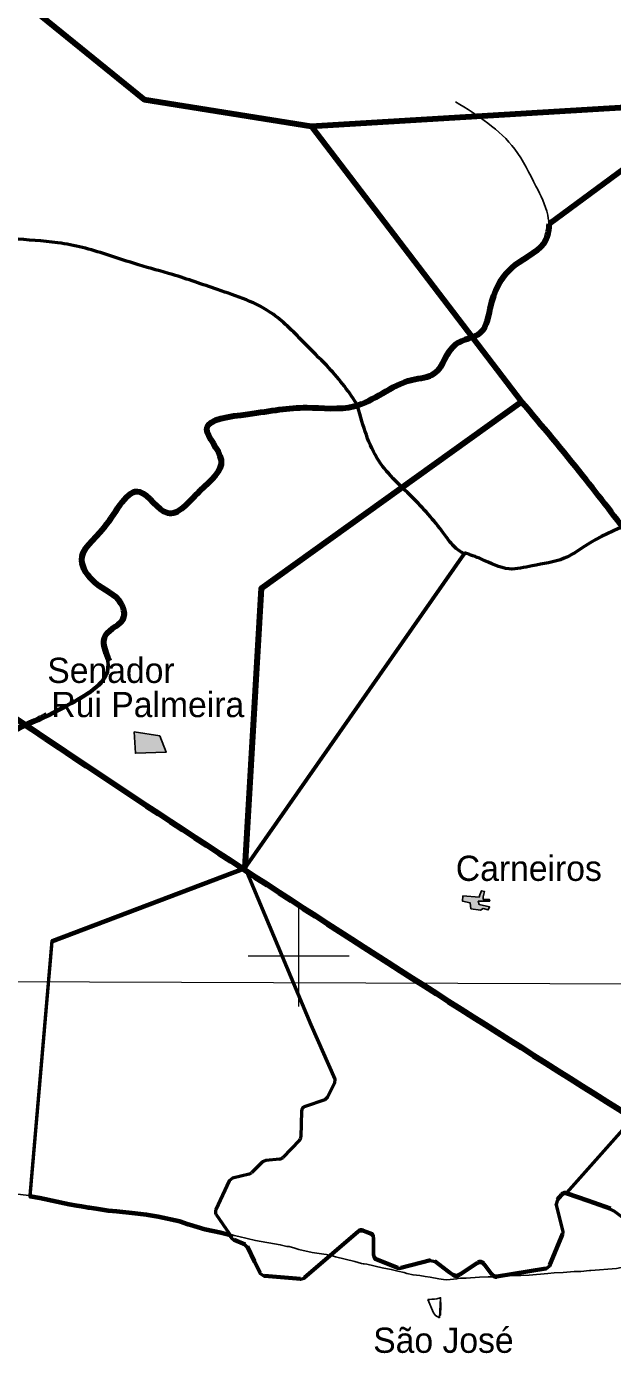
# Model space of a CAD drawing. Extents: x -1643653 to 4543381, y 1624270 to 13878484.
# Drawn here: x 669599 to 681227, y 8942036 to 8968437 of the extents above; entities that cross this region are included whole.
import ezdxf

# ---------------------------------------------------------------- set-up
doc = ezdxf.new("R2010")
doc.units = 0
doc.header["$LTSCALE"] = 200
for name, color, linetype, lineweight in [('1', 7, 'Continuous', 13), ('12', 7, 'Continuous', 25), ('2', 7, 'Continuous', 13), ('21', 7, 'Continuous', 25), ('24', 7, 'Continuous', 25), ('53', 7, 'Continuous', 106), ('58', 7, 'Continuous', 13), ('59', 7, 'Continuous', 53), ('60', 7, 'Continuous', 13), ('9', 7, 'Continuous', 90)]:
    doc.layers.add(name, color=color, linetype=linetype, lineweight=lineweight)
doc.layers.add('41', color=7, linetype='Continuous')

msp = doc.modelspace()

# ---------------------------------------------------------------- hatches: boundary and pattern name
at = {"layer": '21'}
for points in [[(671735.9, 8954446), (671760.9, 8954023.3), (672373, 8954044.2), (672243, 8954367.7)], [(678583.8, 8951169.2), (678261.7, 8951191), (678249.4, 8951088.7), (678404.6, 8951053.3), (678418.7, 8950935.7), (678608.1, 8950907.5), (678661.5, 8950941.2), (678763.6, 8950913.7), (678790.7, 8950974.2), (678582.5, 8951021.4), (678564.1, 8951086), (678791.6, 8951084.1), (678784.3, 8951122), (678663, 8951123.1), (678659.7, 8951172.4), (678690.9, 8951278.2), (678630.4, 8951293.9), (678595.5, 8951210.8)]]:
    msp.add_hatch(color=256, dxfattribs=at).paths.add_polyline_path(points)

# ---------------------------------------------------------------- linework, layer by layer
at = {"layer": '1'}
msp.add_line((565315.3, 8949866.8), (791497.7, 8949052.2), dxfattribs=at)
at = {"layer": '12'}
for points in [[(668899, 8945330), (669255.4, 8945287.2), (669478.1, 8945268.3), (669643.1, 8945246.3), (669863.8, 8945209.3), (670444.9, 8945082.7), (670594.5, 8945054.4), (670690.4, 8945040.8)], [(670690.4, 8945040.8), (670793.7, 8945026.2), (670822.8, 8945019.5)], [(670822.8, 8945019.5), (670847.1, 8945013.9), (670933.2, 8945004.3), (670978.2, 8944997.2)], [(670978.2, 8944997.2), (671219.6, 8944959.2), (671390.7, 8944942.2)], [(671390.7, 8944942.2), (671755.8, 8944906), (671982.5, 8944878.3), (672015.3, 8944872.6)], [(672015.3, 8944872.6), (672208.8, 8944838.9), (672642.8, 8944742.4), (672807.7, 8944686.1), (672835.8, 8944677.4)], [(672835.8, 8944677.4), (673135, 8944584.9), (673452.2, 8944518.2), (673636.9, 8944471), (673680.2, 8944467), (673722.5, 8944456.8), (673814.7, 8944434.5)], [(673814.7, 8944434.5), (674141.4, 8944355.7), (674634.1, 8944270.1), (674766.5, 8944235.9), (674806.9, 8944235.5)], [(674806.9, 8944235.5), (674811.8, 8944235.4), (674924.1, 8944202)], [(674924.1, 8944202), (675002.8, 8944178.6), (675266.7, 8944118.2), (675501.9, 8944084.2)], [(675501.9, 8944084.2), (675549.2, 8944077.4), (675673.7, 8944051.4), (675728.2, 8944031.1), (676117.5, 8943940.8), (676244.7, 8943899.9), (676282.8, 8943893.9), (676298, 8943891.5)], [(676298, 8943891.5), (676354.6, 8943882.5), (676657.8, 8943812.3), (676836.6, 8943782), (676967, 8943748), (677095.8, 8943720.8), (677145.9, 8943703.2), (677271.9, 8943671.8), (677401.8, 8943658.6), (677511.4, 8943642.7)], [(680796, 8943762.2), (681305.7, 8943800.9), (681399.5, 8943819.2), (681734.6, 8943857.4), (681767.5, 8943859.3)], [(677511.4, 8943642.7), (677607.8, 8943628.7), (677782.8, 8943592.4), (677875.1, 8943578.3), (677942.5, 8943578.2)], [(677942.5, 8943578.2), (678138.2, 8943595.7), (678165.3, 8943599.8), (678210.4, 8943606.5)], [(678210.4, 8943606.5), (678223.5, 8943608.4), (678326.7, 8943610.6), (678591.7, 8943628.6), (678760.3, 8943631.9)], [(678760.3, 8943631.9), (678797.8, 8943632.6), (678870.7, 8943637.5)], [(678870.7, 8943637.5), (679230.8, 8943661.7), (679406.8, 8943661.9), (679572.2, 8943670.5), (679942.5, 8943703.3)], [(679942.5, 8943703.3), (680069.1, 8943714.6), (680249.7, 8943722.5), (680468, 8943742.1), (680601.6, 8943742.7), (680771.8, 8943760.4), (680796, 8943762.2)]]:
    msp.add_lwpolyline(points, dxfattribs=at)
at = {"layer": '2'}
for p, q in [((675000, 8949000), (675000, 8951000)), ((674000, 8950000), (676000, 8950000))]:
    msp.add_line(p, q, dxfattribs=at)
at = {"layer": '21'}
for points in [[(671735.9, 8954446), (671760.9, 8954023.3), (672373, 8954044.2), (672243, 8954367.7)], [(678583.8, 8951169.2), (678261.7, 8951191), (678249.4, 8951088.7), (678404.6, 8951053.3), (678418.7, 8950935.7), (678608.1, 8950907.5), (678661.5, 8950941.2), (678763.6, 8950913.7), (678790.7, 8950974.2), (678582.5, 8951021.4), (678564.1, 8951086), (678791.6, 8951084.1), (678784.3, 8951122), (678663, 8951123.1), (678659.7, 8951172.4), (678690.9, 8951278.2), (678630.4, 8951293.9), (678595.5, 8951210.8)]]:
    msp.add_lwpolyline(points, close=True, dxfattribs=at)
for points in [[(677564.5, 8943182.9), (677599.4, 8943181.8), (677648.6, 8943194.1), (677696.2, 8943191), (677743.9, 8943194.8), (677811.3, 8943218), (677815.7, 8943218.5), (677793.3, 8942820.7)], [(677793.3, 8942820.7), (677714, 8942864.2), (677676.2, 8942918.7), (677564.5, 8943182.9)]]:
    msp.add_lwpolyline(points, dxfattribs=at)
at = {"layer": '21', "lineweight": 13}
for points in [[(677818.6, 8943060.4), (677817.1, 8942876.8), (677800.3, 8942857.8), (677789.7, 8942835.5), (677793.3, 8942820.7)], [(677811.4, 8943218.2), (677807.9, 8943209.5), (677818.9, 8943095.6), (677818.6, 8943060.4)]]:
    msp.add_lwpolyline(points, dxfattribs=at)
at = {"layer": '24'}
msp.add_spline([(665209.5, 8949437.1), (665261.8, 8949907.3), (665888.8, 8950560.5), (666750.9, 8951187.5), (667665.3, 8951814.5), (668344.5, 8952363.1), (668788.7, 8952911.7), (669180.6, 8953564.9), (669154.4, 8954270.2), (669755.3, 8954662.1), (670486.8, 8955027.9), (671218.3, 8955785.5), (671166.1, 8956360.3), (671531.8, 8956726), (671479.6, 8956987.3), (670957.1, 8957405.3), (670695.8, 8957849.4), (671139.9, 8958502.5), (671845.3, 8959207.9), (672394, 8958789.9), (673047.1, 8959234), (673465.1, 8959834.9), (673177.7, 8960461.9), (673987.6, 8960749.3), (675163.2, 8960879.9), (676103.7, 8960906.1), (677253.2, 8961428.6), (677697.4, 8961559.2), (678115.4, 8962133.9), (678611.8, 8962369.1), (678820.8, 8962919.9), (679291, 8963704.1), (679918, 8964226.8), (679944.1, 8964697.3), (679709, 8965272.3), (679291, 8966004.2), (678115.4, 8966945.2)], degree=3, dxfattribs=at)
at = {"layer": '53'}
msp.add_line((687996.5, 8970447.8), (679978.5, 8964524.9), dxfattribs=at)
for points in [[(671243.6, 8955851), (671166.1, 8956360.3), (671531.8, 8956726), (671479.6, 8956987.3), (670957.1, 8957405.3), (670695.8, 8957849.4), (671139.9, 8958502.5), (671845.3, 8959207.9), (672394, 8958789.9), (673047.1, 8959234), (673465.1, 8959834.9), (673177.7, 8960461.9), (673987.6, 8960749.3), (675163.2, 8960879.9), (676103.7, 8960906.1), (677253.2, 8961428.6), (677697.4, 8961559.2), (678115.4, 8962133.9), (678611.8, 8962369.1), (678820.8, 8962919.9), (679291, 8963704.1), (679918, 8964226.8), (679978.5, 8964524.9)], [(665209.5, 8949437.1), (665261.8, 8949907.3), (665888.8, 8950560.5), (666750.9, 8951187.5), (667665.3, 8951814.5), (668344.5, 8952363.1), (668788.7, 8952911.7), (669180.6, 8953564.9), (669154.4, 8954270.2), (669755.3, 8954662.1), (670000.9, 8954785.2)]]:
    msp.add_spline(points, degree=3, dxfattribs=at)
at = {"layer": '58'}
for points in [[(676174.9, 8960921), (676168.8, 8960893.4), (676168.8, 8960893.4), (676174.9, 8960894.8)], [(678278.9, 8957978.6), (678286.7, 8957989.8), (678291, 8957999)]]:
    msp.add_lwpolyline(points, dxfattribs=at)
for points in [[(655983.7, 8975399.4), (656923, 8974848.7), (657608.5, 8974464.4), (658343, 8973736.5), (658963.6, 8973136.3), (659596.6, 8972485.1), (660330.5, 8971655.5), (660495.7, 8971591.2), (661115.6, 8970863.8), (661404.1, 8970086.9), (661693.8, 8969526.2), (662110.5, 8968901.3), (662312.2, 8968544.4), (662816.6, 8967664.9), (663042.2, 8967040.8), (663203.6, 8966302.6), (663365.3, 8965640.7), (663833.2, 8965053.8), (664099.5, 8964849.2), (664772, 8964426.8), (665496.3, 8964144), (666463.4, 8964000.2), (667623.1, 8964148), (668184.3, 8964285.6), (669317.4, 8964230), (670221.1, 8964150), (671187.7, 8963917.1), (671823.3, 8963711.1), (672497.1, 8963517.5), (673386.9, 8963221.4), (674492.1, 8962733.6), (675125.5, 8962146), (675556, 8961711.9), (676150.3, 8960959.1), (676174.9, 8960921)], [(676174.9, 8960894.8), (676589.7, 8959824.8), (677298.5, 8959058.9), (677905.7, 8958344.2), (678108.1, 8958101.8), (678278.9, 8957978.6)], [(678291, 8957999), (678628.8, 8957871.5), (679175.3, 8957678.5), (679634.1, 8957740.2), (680271.7, 8957890.1), (680680.6, 8958130.1), (682556.7, 8958821.8), (683435.7, 8958881.7), (684580.7, 8958673.6), (685598.3, 8958453.2)]]:
    msp.add_spline(points, degree=3, dxfattribs=at)
at = {"layer": '59'}
for p, q in [((675713, 8947474.9), (675575.4, 8947196.5)), ((675517.3, 8947145.9), (675125.9, 8947015.5)), ((675057.6, 8946923.6), (675042.4, 8946412.2)), ((675057.6, 8946923.6), (675042.4, 8946412.2)), ((675014.8, 8946346.2), (674685, 8946000.3)), ((675014.8, 8946346.2), (674685, 8946000.3)), ((674283.9, 8945916), (674062, 8945697.8)), ((674621.8, 8945969.8), (674344.8, 8945944.2)), ((674015.4, 8945671.9), (673688.4, 8945593)), ((673621.4, 8945538.3), (673355.6, 8944972)), ((680134, 8945176.2), (680214.2, 8945273)), ((673363.7, 8944872.9), (673675, 8944419.4)), ((673363.7, 8944872.9), (673640.2, 8944470.1)), ((680241.8, 8944556.7), (680113.8, 8945089)), ((673716.6, 8944384.7), (673935.5, 8944286.7)), ((675110.8, 8943630.1), (676179.1, 8944546.1)), ((676280.2, 8944563.4), (676422.8, 8944508.3)), ((676422.8, 8944482.2), (676280.2, 8944537.3)), ((676486.8, 8944415.1), (676486.8, 8944082.3)), ((676486.8, 8944056.2), (676486.8, 8944388.9)), ((679978.9, 8943872.2), (680237, 8944495.1)), ((676550.7, 8943989.1), (676967.6, 8943827.5)), ((677029.2, 8943824), (677616.1, 8943978.3)), ((678196.5, 8943692), (678546.5, 8943924.4)), ((678546.5, 8943898.2), (678196.5, 8943665.9)), ((678682.2, 8943900.5), (678836.2, 8943692)), ((678836.2, 8943665.9), (678682.2, 8943874.3)), ((678932.8, 8943652.8), (679902.7, 8943811.8)), ((674319.5, 8943668.1), (675037.1, 8943606.4))]:
    msp.add_line(p, q, dxfattribs=at)
for points in [[(670690.4, 8945014.6), (670594.5, 8945028.2), (670444.9, 8945056.6), (669863.8, 8945183.2), (669668.8, 8945215.8), (669670.4, 8945225.3), (670109.7, 8950279.6), (673931.9, 8951728.3), (678286.7, 8957963.6), (678291, 8957972.9)], [(678286.7, 8957989.8), (673931.9, 8951754.5), (675240.6, 8948634.2)], [(680324.2, 8945303.6), (688585, 8954592.4), (688741.1, 8957552.5)], [(680324.2, 8945303.6), (688585, 8954592.4), (688741.1, 8957552.5)], [(669670.4, 8945251.4), (670109.7, 8950305.8), (673931.9, 8951754.5)], [(673931.9, 8951754.5), (675240.6, 8948634.2), (675717.3, 8947553.5)], [(675240.6, 8948634.2), (675717.3, 8947553.5), (675713, 8947474.9), (675575.4, 8947196.5), (675517.3, 8947145.9), (675125.9, 8947015.5)], [(674621.8, 8945969.8), (674344.8, 8945944.2), (674283.9, 8945916), (674062, 8945697.8)], [(674015.4, 8945671.9), (673688.4, 8945593), (673621.4, 8945538.3), (673355.6, 8944972)], [(670690.4, 8945040.8), (670594.5, 8945054.4), (670444.9, 8945082.7), (669863.8, 8945209.3), (669668.8, 8945241.9)], [(680214.2, 8945246.8), (680134, 8945150.1), (680113.8, 8945062.9), (680241.8, 8944530.5), (680237, 8944468.9), (679978.9, 8943846), (679902.7, 8943785.6), (678932.8, 8943626.6)], [(681194.6, 8944999.3), (680745, 8945156.4), (680324.2, 8945303.6)], [(684892.7, 8942987.2), (684448.1, 8942951.1), (684389.5, 8942964.5), (683513.2, 8943477.6), (683428.9, 8943485.5), (683149.4, 8943385.1), (683078.6, 8943386.3), (681940.2, 8943839.3), (681879.7, 8943909.7), (681729.7, 8944557.4), (681692.2, 8944614.9), (681259.8, 8944938.4), (681194.6, 8944973.1), (680745, 8945130.3), (680324.2, 8945277.4)], [(670822.8, 8945019.5), (670793.7, 8945026.2), (670690.4, 8945040.8)], [(670822.8, 8944993.3), (670793.7, 8945000), (670690.4, 8945014.6)], [(670978.2, 8944997.2), (670933.2, 8945004.3), (670847.1, 8945013.9), (670822.8, 8945019.5)], [(670978.2, 8944971.1), (670933.2, 8944978.2), (670847.1, 8944987.8), (670822.8, 8944993.3)], [(671390.7, 8944942.2), (671219.6, 8944959.2), (670978.2, 8944997.2)], [(671390.7, 8944916.1), (671219.6, 8944933), (670978.2, 8944971.1)], [(672015.3, 8944872.6), (671982.5, 8944878.3), (671755.8, 8944906), (671390.7, 8944942.2)], [(672015.3, 8944846.5), (671982.5, 8944852.2), (671755.8, 8944879.8), (671390.7, 8944916.1)], [(672835.8, 8944677.4), (672807.7, 8944686.1), (672642.8, 8944742.4), (672208.8, 8944838.9), (672015.3, 8944872.6)], [(672835.8, 8944651.2), (672807.7, 8944659.9), (672642.8, 8944716.3), (672208.8, 8944812.7), (672015.3, 8944846.5)], [(673640.2, 8944470.7), (673636.9, 8944471), (673452.2, 8944518.2), (673135, 8944584.9), (672835.8, 8944677.4)], [(673640.2, 8944444.5), (673636.9, 8944444.8), (673452.2, 8944492.1), (673135, 8944558.8), (672835.8, 8944651.2)], [(676179.1, 8944519.9), (675110.8, 8943603.9), (675037.1, 8943580.2), (674319.5, 8943642), (674238.3, 8943697.5), (674125.3, 8943927.1), (673984.4, 8944213.4), (673935.5, 8944260.6), (673716.6, 8944358.5), (673675, 8944393.2), (673640, 8944444.3), (673640.2, 8944444.5)], [(673984.4, 8944239.6), (674125.3, 8943953.3), (674238.3, 8943723.6)], [(678045.7, 8943671.1), (677962, 8943735.4), (677702.4, 8943934.8), (677616.1, 8943952.2), (677029.2, 8943797.8), (676967.6, 8943801.3), (676550.7, 8943962.9)], [(677702.4, 8943960.9), (677962, 8943761.6), (678045.7, 8943697.2)]]:
    msp.add_lwpolyline(points, dxfattribs=at)
for centre, radius, start, end in [((675157.6, 8946920.6), 100, 108.43497, 178.29512), ((675157.6, 8946920.6), 100, 108.43497, 178.29723), ((674942.5, 8946415.2), 100, 316.36201, 358.29723), ((674612.7, 8946069.4), 100, 275.26498, 316.36201), ((673991.9, 8945769.1), 100, 283.57688, 314.51592), ((673991.9, 8945769.1), 100, 283.57688, 314.51592), ((680291.2, 8945209.2), 100, 70.7277, 140.34605), ((680291.2, 8945183), 100, 70.7277, 140.34605), ((673446.2, 8944929.5), 100, 154.86041, 214.46341), ((676244.1, 8944470.2), 100, 68.88566, 130.61183), ((676244.1, 8944444), 100, 68.88566, 130.61183), ((676386.8, 8944415.1), 100, 0, 68.88566), ((676386.8, 8944388.9), 100, 0, 68.88566), ((676586.8, 8944082.3), 100, 180, 248.81474), ((676586.8, 8944056.2), 100, 180, 248.81474), ((678601.8, 8943841.1), 100, 36.45572, 123.58272), ((678601.8, 8943814.9), 100, 36.45572, 123.58272), ((678124.8, 8943800.1), 129.8, 232.47373, 303.58145), ((678124.8, 8943774), 129.8, 232.47373, 303.58145), ((678916.6, 8943751.5), 100, 216.45573, 279.30864), ((678916.6, 8943725.3), 100, 216.45573, 279.30864)]:
    msp.add_arc(centre, radius, start, end, dxfattribs=at)
for points in [[(676174.9, 8960921), (676150.3, 8960959.1), (675556, 8961711.9), (675125.5, 8962146), (674492.1, 8962733.6), (673386.9, 8963221.4), (672497.1, 8963517.5), (671823.3, 8963711.1), (671187.7, 8963917.1), (670221.1, 8964150), (669317.4, 8964230), (668184.3, 8964285.6), (667623.1, 8964148), (666463.4, 8964000.2), (665496.3, 8964144), (664772, 8964426.8), (664099.5, 8964849.2), (663833.2, 8965053.8), (663365.3, 8965640.7), (663203.6, 8966302.6), (663042.2, 8967040.8), (662816.6, 8967664.9), (662312.2, 8968544.4), (662110.5, 8968901.3), (661693.8, 8969526.2), (661404.1, 8970086.9), (661115.6, 8970863.8), (660495.7, 8971591.2), (660330.5, 8971655.5), (659596.6, 8972485.1), (658963.6, 8973136.3), (658343, 8973736.5), (657608.5, 8974464.4), (656923, 8974848.7), (655983.7, 8975399.4)], [(665209.5, 8949437.1), (665261.8, 8949907.3), (665888.8, 8950560.5), (666750.9, 8951187.5), (667665.3, 8951814.5), (668344.5, 8952363.1), (668788.7, 8952911.7), (669180.6, 8953564.9), (669154.4, 8954270.2), (669755.3, 8954662.1), (670486.8, 8955027.9), (671218.3, 8955785.5), (671166.1, 8956360.3), (671531.8, 8956726), (671479.6, 8956987.3), (670957.1, 8957405.3), (670695.8, 8957849.4), (671139.9, 8958502.5), (671845.3, 8959207.9), (672394, 8958789.9), (673047.1, 8959234), (673465.1, 8959834.9), (673177.7, 8960461.9), (673987.6, 8960749.3), (675163.2, 8960879.9), (676103.7, 8960906.1), (676174.9, 8960921)], [(676174.9, 8960894.8), (676103.7, 8960879.9), (675163.2, 8960853.8), (673987.6, 8960723.2), (673177.7, 8960435.8), (673465.1, 8959808.8), (673047.1, 8959207.9), (672394, 8958763.8), (671845.3, 8959181.8), (671139.9, 8958476.4), (670695.8, 8957823.2), (670957.1, 8957379.1), (671479.6, 8956961.1), (671531.8, 8956699.9), (671166.1, 8956334.1), (671218.3, 8955759.3), (670486.8, 8955001.7), (669755.3, 8954636), (669154.4, 8954244.1), (669180.6, 8953538.7), (668788.7, 8952885.6), (668344.5, 8952337), (667665.3, 8951788.3), (666750.9, 8951161.3), (665888.8, 8950534.3), (665261.8, 8949881.2), (665209.5, 8949410.9)], [(678291, 8957972.9), (678108.1, 8958101.8), (677905.7, 8958344.2), (677298.5, 8959058.9), (676589.7, 8959824.8), (676174.9, 8960894.8)], [(685598.3, 8958453.2), (684580.7, 8958673.6), (683435.7, 8958881.7), (682556.7, 8958821.8), (680680.6, 8958130.1), (680271.7, 8957890.1), (679634.1, 8957740.2), (679175.3, 8957678.5), (678628.8, 8957871.5), (678291, 8957999)]]:
    msp.add_spline(points, degree=3, dxfattribs=at)
at = {"layer": '60', "lineweight": 25}
msp.add_spline([(814781, 9009175.5), (814787.2, 9009173.4), (814796.9, 9009173.4), (814799.4, 9009172.4), (814805.1, 9009174.5), (814805.6, 9009176.5), (814811.7, 9009179.5), (814811.7, 9009179.5), (814801.5, 9009181), (814790.7, 9009181.5), (814784.1, 9009183.1), (814777.4, 9009185.1), (814778.4, 9009175.5)], degree=3, dxfattribs=at)
at = {"layer": '9'}
for points in [[(657923.9, 8974844.3), (666205.7, 8971636.3), (671933.6, 8966993.4), (675245, 8966459.9), (693230.3, 8967549.5), (697027.9, 8970867.6)], [(675245, 8966459.9), (679425.4, 8960995.9), (674256, 8957288.3), (673931.9, 8951754.5)]]:
    msp.add_lwpolyline(points, dxfattribs=at)
for points in [[(637260.6, 8972975.8), (641524.5, 8971056.2), (652526.1, 8965412.7), (653164.3, 8965062.8), (670790.5, 8953770.1), (686194, 8943929.9), (696283.3, 8937647.1)], [(694874, 8947402.7), (694491.4, 8947729), (693981.6, 8948105.1), (692654.2, 8949437.3), (691811.8, 8950292), (691552.9, 8951277.6), (691093.4, 8951755.3), (689976, 8951721.8), (689441.2, 8951996.3), (689158.9, 8952576.6), (688699.5, 8953029), (687605.5, 8953400.8), (685873.4, 8954400.8), (684752.3, 8955101.5), (681638, 8958243.7), (680641.1, 8959527.7), (679425.4, 8960995.9)]]:
    msp.add_spline(points, degree=3, dxfattribs=at)

# ---------------------------------------------------------------- texts
at = {"layer": '41'}
for s, p in [('Senador', (670009.9, 8955416.6)), ('Rui Palmeira', (670091.2, 8954738.2)), ('Carneiros', (678119, 8951489.4)), ('São José', (676479.4, 8942126.7))]:
    msp.add_text(s, height=500, dxfattribs=at).set_placement(p)

doc.saveas('drawing.dxf')
